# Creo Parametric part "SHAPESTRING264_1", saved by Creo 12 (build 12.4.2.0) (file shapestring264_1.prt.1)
Units: Custom; MM, KILOGRAM, SECS

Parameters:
  PTC_WM_ITERATION = "0"
  PTC_WM_VERSION = "-.0"
  PTC_WM_LIFECYCLE_STATE = "In Work"
  PTC_WM_LIFECYCLE = "MO_CADDocument"
  PTC_WM_CREATED_BY = "Maximilian Roepper (Z0017RMS: MO)"
  PTC_WM_CREATED_ON = "18-Sep-26 11:36:42 AM"
  PTC_WM_MODIFIED_BY = "Maximilian Roepper (Z0017RMS: MO)"
  PTC_WM_MODIFIED_ON = "18-Sep-26 11:36:46 AM"
  PDMLINKNUMBER = "PDM000071455042"
  PTC_WM_NAME = "shapestring264_1.prt"
  PTC_WM_NUMBER = "PDM000071455042"

Other parameters: WEIGHT, WEIGHT_FACTOR, WEIGHT_ADD, _MASS_TEMP, _DIFF_TEMP, MC_ERRORS, SUPPLIER

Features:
  1. coordinate system
  2. datum plane "PRT_YZ"
  3. datum plane "PRT_XY"
  4. datum plane "PRT_XZ"
  5. coordinate system
  6. datum axis
  7. datum axis
  8. datum axis
  9. coordinate system
  10. imported feature
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
Other named items: PRT, SIEMENS_MO, DRW_VIEW_ORG, PRT_X, PRT_Y, PRT_Z, CS0, ROUGH_GROB

Layers: 00_STD_CSYS-KSYS, 01_STD_PLANES-EBENEN, 02_STD_AXES-ACHSEN, 03_STD_CSYS-KSYS, 24_IMPORT_FEAT-IMPORT_KE, WHITE

Surfaces: 1 plane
